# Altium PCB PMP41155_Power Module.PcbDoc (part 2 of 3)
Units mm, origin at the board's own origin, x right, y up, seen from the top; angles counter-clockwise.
Board outline 40.5 x 74.05 mm, 8 copper layers (Top Layer, Layer 1, Layer 2, Layer 3, Layer 4, Layer 5, Layer 6, Bottom Layer), stack 1.58 mm thick; 130 components, 51 nets, 407 pads, 560 vias.
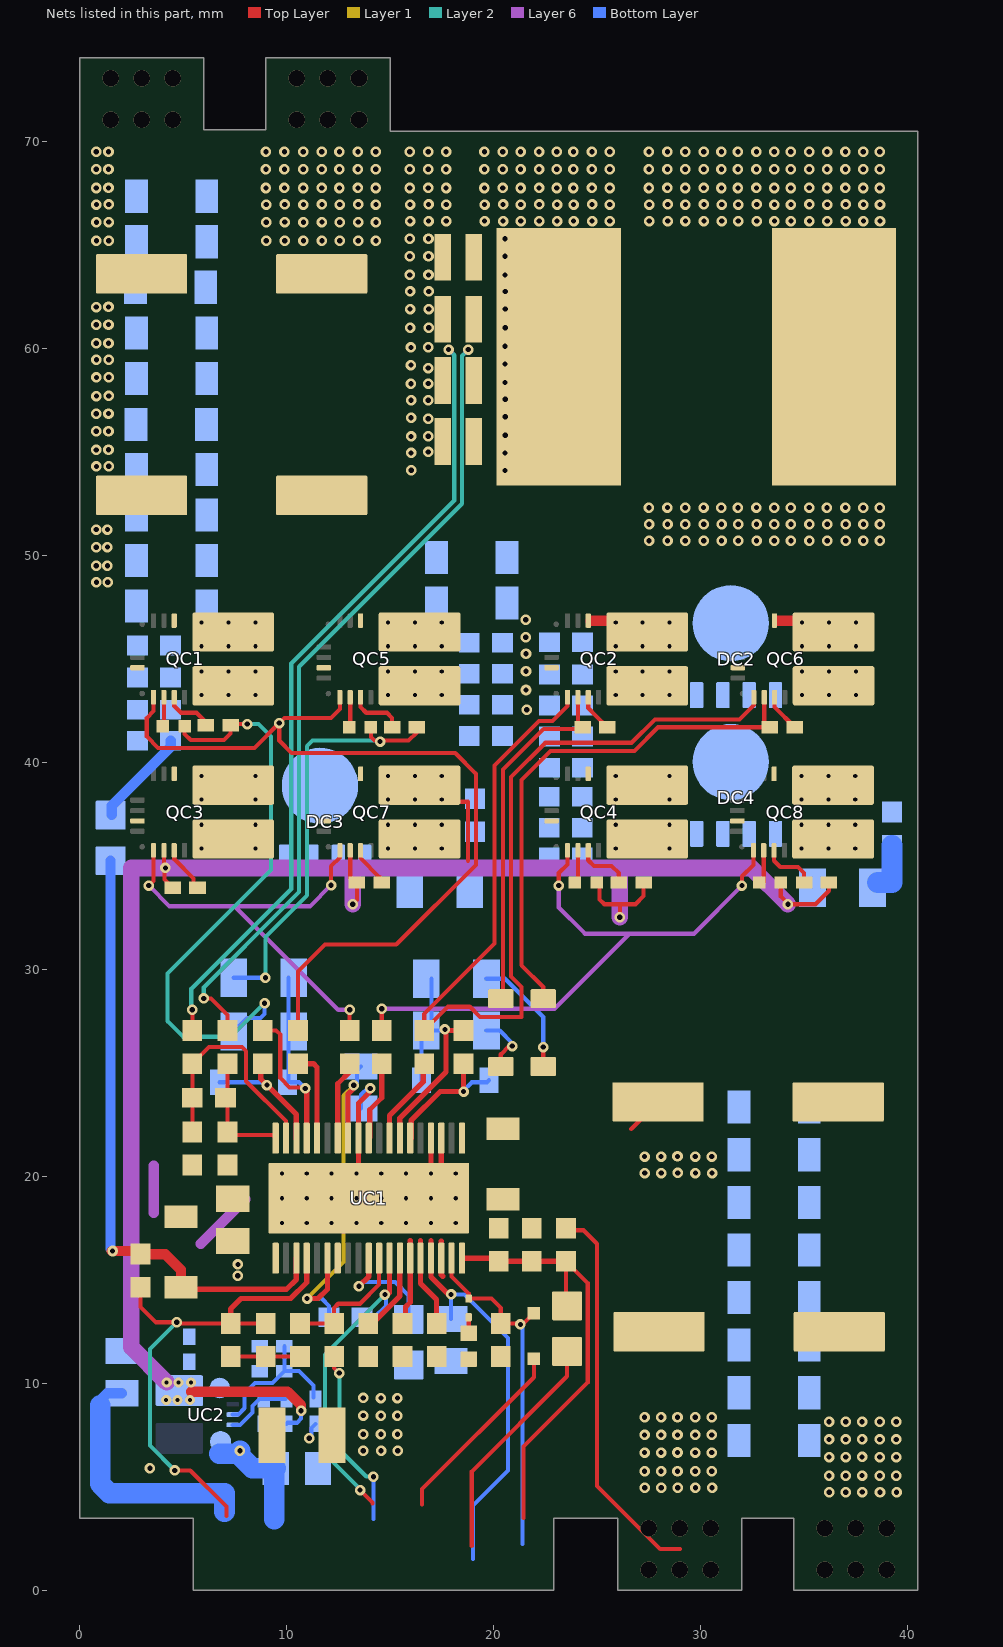
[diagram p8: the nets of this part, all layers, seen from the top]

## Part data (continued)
CC47: "CAP, CERM, 68 pF, 50 V,+/- 5%, C0G/NP0, 0603", Cap_Case=0603, Manufacturer=AVX, Supplier Part Number 1=478-1173-1-ND, TempCo=C0G/NP0, Tolerance_%=5, Value1="0.144 ohm", Value2=50V, ValueDisplayed=68pF
CC49: "CAP, CERM, 1000 pF, 50 V,+/- 5%, C0G/NP0, 0603", Cap_Case=0603, Manufacturer=MuRata, Supplier Part Number 1=490-1451-1-ND, TempCo=C0G/NP0, Tolerance_%=5, Value2=50V, ValueDisplayed=1000pF
CC50 CC51: library part CMP-0006939-4, "CAP, CERM, 47 pF, 50 V, +/- 5%, C0G/NP0, 0603", Cap_Case=0603, Manufacturer=Kemet, Supplier Part Number 1=399-1056-1-ND, TempCo=C0G/NP0, Tolerance_%=5%, Value1=Unknown, Value2=50V, ValueDisplayed=47pF
CC52: "CAP, CERM, 2200 pF, 50 V,+/- 10%, X5R, 0603", Cap_Case=0603, Manufacturer=MuRata, Supplier Part Number 1=GRM188R61H222KA01D-ND, TempCo=X5R, Tolerance_%=10, Value2=50V, ValueDisplayed=2200pF
CC53 CC54: library part CMP-0007135-4, "CAP, CERM, 0.1 uF, 16 V, +/- 10%, X7R, AEC-Q200 Grade 1, 0603", Cap_Case=0603, Manufacturer=MuRata, Supplier Part Number 1=490-8015-1-ND, TempCo=X7R, Tolerance_%=10%, Value1=Unknown, Value2=16V, ValueDisplayed=0.1uF
CC55: library part CMP-0009211-1, "CAP, CERM, 47 uF, 16 V, +/- 10%, X5R, 1210", Cap_Case=1210, Manufacturer=MuRata, Supplier Part Number 1=GRM32ER61C476KE15L-ND, TempCo=X5R, Tolerance_%=10%, Value1=Unknown, Value2=16V, ValueDisplayed=47uF
CC56: library part CMP-0007728-2, "CAP, CERM, 1 uF, 25 V, +/- 10%, X7R, 0805", Cap_Case=0805, Manufacturer=Kemet, Supplier Part Number 1=399-8004-1-ND, TempCo=X7R, Tolerance_%=10%, Value1=Unknown, Value2=25V, ValueDisplayed=1uF
CC57: library part CMP-0007989-2, "CAP, CERM, 22 uF, 6.3 V, +/- 10%, X5R, 0805", Cap_Case=0805, Manufacturer="Samsung Electro-Mechanics", TempCo=X5R, Tolerance_%=10%, Value1=Unknown, Value2=6.3V, ValueDisplayed=22uF
CC58: "CAP, CERM, 0.1uF, 6.3V, +/-10%, X7R, 0402", Cap_Case=0402, Manufacturer=MuRata, Supplier Part Number 1=GRM155R70J104KA01D-ND, TempCo=X7R, Tolerance_%=10, Value1=Unknown, Value2=6.3V, ValueDisplayed=0.1uF
CC59: library part CMP-0078218-1, "CAP, CERM, 0.01 µF, 16 V,+/- 10%, X7R, 0402", Cap_Case=0402, Manufacturer=Kemet, Supplier Part Number 1=399-1038-1-ND, TempCo=X7R, Tolerance_%=10%, Value2=16V, ValueDisplayed=0.01µF
CC60: library part CMP-0095696-1, "Cap Ceramic 22nF 50V X7R ±10% Pad SMD 0603 +125°C T/R", Manufacturer=Samsung, Operating Temperature Range="-55°C to +125°C", TempCo=0.15, Temperature Characteristic=X7R, Tolerance_%=10%, ValueDisplayed=22nF
CC61: library part CMP-0007168-4, "CAP, CERM, 820 pF, 25 V, +/- 5%, C0G/NP0, 0603", Cap_Case=0603, Manufacturer=MuRata, Supplier Part Number 1=81-GRM185C1E821JA01D, TempCo=C0G/NP0, Tolerance_%=5%, Value1=Unknown, Value2=25V, ValueDisplayed=820pF
CC62: library part CMP-0007572-2, "CAP, CERM, 0.22 uF, 25 V, +/- 20%, X7R, 0805", Cap_Case=0805, Manufacturer=AVX, Supplier Part Number 1=478-3757-1-ND, TempCo=X7R, Tolerance_%=20%, Value1="0.016 ohm", Value2=25V, ValueDisplayed=0.22uF
D1: library part CMP-0029006-2, "Diode, Ultrafast, 100 V, 0.25 A, SOD-323", Manufacturer=Nexperia, Value1=0.25A, Value2=1.4V
DC1 DC7: library part CMP-0090564-1, "Diode Schottky 40V 500mA Surface Mount SOD-123", Digikey Part Number=NRVB0540T1GOSCT-ND, Forward Current=0.5A, Manufacturer="On Semiconductor", Max Surge Forward Current=5.5A, Mouser Part Number=863-NRVB0540T1G, Operating Temperature Range="-55°C to +150°C", Peak Reverse Current=20uA
DC2 DC3 DC4: library part CMP-0032275-1, "Diode 100 V 30A Surface Mount PowerFlat™ (5x6)", Digikey Part Number=497-10342-1-ND, Forward Current=30A, Manufacturer=STMicroelectronics, Max Surge Forward Current=200A, Mouser Part Number=511-STPS30M100DJF-TR, Operating Temperature Range="to +150°C", Peak Reverse Current=100uA
DC5 DC6: library part CMP-0077600-3, "Diode, Zener, 5.6 V, 500 mW, SOD-123", Manufacturer=Vishay-Semiconductor, Power_W=500mW, Value1=0.5W
LC1: library part CMP-0064042-1, ValueDisplayed=2.2uH
LOGO1: library part CMP-0074837-1, "IEC 61010-1 Hot Surface Warning"
Logo2: library part Pb-Free
Logo3: library part CMP-0074769-1
Logo4: library part CMP-0074847-1, "FCC_disclaimer"
QC1 QC2 QC3 QC4 QC5 QC6 QC7 QC8: library part CMP-0037654-1, "100-V, 64-A GaN with Integrated Driver", Manufacturer="Texas Instruments", Max Supply Voltage=5.25V, Min Supply Voltage=4.75V, Nominal Supply Current=3mA, Operating Temperature Range="-40°C to +125°C"
R1 R2 R7 R8: library part CMP-02407-004899-1, "RES Thick Film, 3.01Ω, 1%, 0.063W, 200ppm/°C, 0402", Case Code (Imperial)=0402, Case Code (Metric)=1005, Max Operating Temperature=155°C, Max Power Dissipation=63mW, Min Operating Temperature=-55°C, Package Quantity=10000, Resistance=3.01R, Temperature Coefficient=200ppm/°C, Tolerance=1%, Voltage Rating=50V
R3 R4: library part CMP-0016888-3, "RES, 2.55, 1%, 0.25 W, AEC-Q200 Grade 0, 1206", Manufacturer=Vishay-Dale, Power_W=250mW, Supplier Part Number 1=541-2.55FFCT-ND, TempCo="100 ppm/C", Tolerance_%=1%, Value2=0.25W, Value_Code=2R55, ValueDisplayed=2.55
R5: library part CMP-0022550-4, "RES, 681 k, 1%, 0.1 W, AEC-Q200 Grade 0, 0603", Manufacturer=Vishay-Dale, Power_W=100mW, Supplier Part Number 1=541-681KHCT-ND, TempCo="100 ppm/C", Tolerance_%=1%, Value2=0.1W, Value_Code=681k
R6: library part CMP-0022042-4, "RES, 13.0 k, 1%, 0.1 W, AEC-Q200 Grade 0, 0603", Manufacturer=Vishay-Dale, Power_W=100mW, Supplier Part Number 1=541-13.0KHCT-ND, TempCo="100 ppm/C", Tolerance_%=1%, Value2=0.1W, Value_Code=13k0, ValueDisplayed=13.0k
RC1 RC2 RC26 RC27: library part CMP-0018270-2, "RES, 3.30, 1%, 0.25 W, 1206", Manufacturer="Yageo America", Power_W=250mW, Supplier Part Number 1=311-3.30FRCT-ND, TempCo="200 ppm/C", Tolerance_%=1%, Value2=0.25W, Value_Code=3R30, ValueDisplayed=3.30
RC3 RC4 RC28 RC29: library part CMP-0015357-3, "RES, 0.002, 2%, 1 W, 0508", Manufacturer="Susumu Co Ltd", Power_W=1W, Supplier Part Number 1=408-1592-1-ND, TempCo="100 ppm/C", Tolerance_%=2%, Value_Code=2L000, ValueDisplayed=0.002
RC5 RC6 RC18: library part CMP-0096818-1, "0 Ohms Jumper 0.245W Chip Resistor 0805 (2012 Metric) - Metal Element", Digikey Part Number=JR0805X35ECT-ND, Manufacturer=Ohmite, Mouser Part Number=588-JR0805X35E, Operating Temperature Range="-55°C to +150°C", Power_W=245mW
RC7: "RES, 270 k, 5%, 0.1 W, 0603", Manufacturer=Vishay-Dale, Power_W=0.1, Supplier Part Number 1=541-270KGCT-ND, TempCo="200 ppm/C", Tolerance_%=5, Value1=5%, Value2=0.1W, Value_Code=270k
RC8 RC10: "RES, 100, 1%, 0.1 W, 0603", Manufacturer="Yageo America", Power_W=0.1, Supplier Part Number 1=311-100HRCT-ND, TempCo="200 ppm/C", Tolerance_%=1, Value1=1%, Value2=0.1W, Value_Code=100R, ValueDisplayed=100
RC9: "RES, 10.0 k, 1%, 0.1 W, 0603", Manufacturer=Vishay-Dale, Power_W=0.1, Supplier Part Number 1=541-10.0KHCT-ND, TempCo="100 ppm/C", Tolerance_%=1, Value1=1%, Value2=0.1W, Value_Code=10k0, ValueDisplayed=10.0k
RC11: "RES, 100, 1%, 0.1 W, 0603", Manufacturer=Vishay-Dale, Power_W=0.1, Supplier Part Number 1=541-100HCT-ND, TempCo="100 ppm/C", Tolerance_%=1, Value1=1%, Value2=0.1W, Value_Code=100R, ValueDisplayed=100
RC12: "RES, 10.7 k, 1%, 0.1 W, 0603", Manufacturer=Vishay-Dale, Power_W=0.1, Supplier Part Number 1=541-10.7KHCT-ND, TempCo="100 ppm/C", Tolerance_%=1, Value1=1%, Value2=0.1W, Value_Code=10k7, ValueDisplayed=10.7k
RC13 RC14 RC16 RC19: library part CMP-0025697-4, "RES, 0, 5%, 0.1 W, AEC-Q200 Grade 0, 0603", Manufacturer=Vishay-Dale, Power_W=100mW, Supplier Part Number 1=541-0.0GCT-ND, TempCo="200 ppm/C", Tolerance_%=5%, Value2=0.1W, Value_Code=0000, ValueDisplayed=0
RC15: library part CMP-0026403-2, "RES, 49.9 k, 1%, 0.063 W, AEC-Q200 Grade 0, 0402", Manufacturer=Vishay-Dale, Power_W=63mW, Supplier Part Number 1=541-49.9KLCT-ND, TempCo="100 ppm/C", Tolerance_%=1%, Value2=0.063W, Value_Code=49k9, ValueDisplayed=49.9k
RC17: library part CMP-0026728-1, "RES, 220 k, 1%, 0.0625 W, 0402", Manufacturer="Yageo America", Power_W=62.5mW, Supplier Part Number 1=311-220KLRCT-ND, TempCo="100 ppm/C", Tolerance_%=1%, Value2=0.0625W, Value_Code=220k
RC20 RC21: library part CMP-0078244-2, "RES, 30.0 k, 1%, 0.063 W, AEC-Q200 Grade 0, 0402", Manufacturer=Vishay-Dale, Power_W=63mW, Supplier Part Number 1=541-30.0KLCT-ND, TempCo="100 ppm/C", Tolerance_%=1%, Value2=0.063W, Value_Code=30k0, ValueDisplayed=30.0k
RC22: library part CMP-0089989-1, "2.87 kOhms ±1% 0.1W, 1/10W Chip Resistor 0402 (1005 Metric) Automotive AEC-Q200, Moisture Resistant Thick Film", Digikey Part Number=2019-RK73H1ETTP2871FCT-ND, Manufacturer="KOA Speer", Mouser Part Number=660-RK73H1ETTP2871F, Operating Temperature Range="-55°C to +155°C", Power_W=100mW, TempCo=100ppm/°C, Tolerance_%=1%
RC23: "RES, 8.25 k, 1%, 0.1 W, 0603", Manufacturer=Vishay-Dale, Power_W=0.1, Supplier Part Number 1=541-8.25KHCT-ND, TempCo="100 ppm/C", Tolerance_%=1, Value1=1%, Value2=0.1W, Value_Code=8k25, ValueDisplayed=8.25k
RC24: "RES, 100 k, 1%, 0.1 W, 0603", Manufacturer=Vishay-Dale, Power_W=0.1, Supplier Part Number 1=541-100KHCT-ND, TempCo="100 ppm/C", Tolerance_%=1, Value1=1%, Value2=0.1W, Value_Code=100k
RC25: library part CMP-0022064-4, "RES, 158 k, 1%, 0.1 W, AEC-Q200 Grade 0, 0603", Manufacturer=Vishay-Dale, Power_W=100mW, Supplier Part Number 1=541-158KHCT-ND, TempCo="100 ppm/C", Tolerance_%=1%, Value2=0.1W, Value_Code=158k
UC1: library part CMP-0094661-2, "Wide VIN Bidirectional 4 Switch Buck-Boost Controller", Manufacturer="Texas Instruments", Max Supply Voltage=78V, Min Supply Voltage=2.8V, Nominal Supply Current=25uA, Operating Temperature Range="-40°C to +125°C", Output Voltage=3.3-78V, Switching Frequency=100-2000kHz
UC2: library part CMP-0097277-1, "3V to 16 V Input, 3-A Synchronous Step-Down Voltage Regulator Module, QFN-FCMOD7", Manufacturer="Texas Instruments", Max Supply Voltage=16V, Min Supply Voltage=3V, Nominal Supply Current=120-400uA, Operating Temperature Range="-40°C to +125°C", Output Voltage=0.6-7V, Switching Frequency=1400/2000kHz

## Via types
v1: diameter 0.508, hole 0.254, Top Layer to Bottom Layer, 408 vias
v2: diameter 0.5, hole 0.2, Top Layer to Bottom Layer, tented both sides, 88 vias
v3: diameter 0.5, hole 0.2, Top Layer to Bottom Layer, 36 vias
v4: diameter 0.8, hole 0.8, Top Layer to Bottom Layer, 24 vias
v5: diameter 0.508/0.508/0.508/0.508/0.508/0.508/0.508/0.508 (per signal layer), hole 0.254, Top Layer to Bottom Layer, 4 vias

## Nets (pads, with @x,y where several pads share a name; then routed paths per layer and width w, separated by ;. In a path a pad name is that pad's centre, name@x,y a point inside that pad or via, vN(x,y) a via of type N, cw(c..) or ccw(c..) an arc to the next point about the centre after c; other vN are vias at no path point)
5V: CC41.1 CC42.1 CC57.1 CC58.1 CC65.1 CC66.1 QC3.3 QC7.3 R2.2 R8.2 RC17.2 UC2.3 | length 95.1
  Top Layer w0.2: QC3.3@4.075,35.75 4.075,34.975 v1(4.15,34.9) 4.1,34.85 4.1,34.35 CC41.1@4.3,34.15 ; 5.385,9.6 v3(5.385,10.05) ; QC7.3@13.075,35.75 13.075,34.425 CC65.1@13.3,34.2 ; v1(13.2,33.15) 13.4,33.35 13.4,34 13.3,34.1 CC65.1@13.4,34.2 ; R2.2@25.125,34.2 25.125,33.375 25.35,33.15 26.1,33.15 ; v1(26.1,32.518) 26.1,33.15 ; CC42.1@27.25,34.2 27.25,33.55 26.85,33.15 26.1,33.15 ; R8.2@33.875,34.2 33.875,33.525 v1@34.25,33.15 ; v1(34.218,33.15) v1@34.234,33.166 ; v1@34.35,33.15 35.55,33.15 36.2,33.8 CC66.1@36.2,34.2
  Top Layer w0.5: 5.385,9.6 10.05,9.6 10.7,8.95 v1(10.7,8.687)
  Layer 6 w0.5: 22.25,34.75 22.4,34.9 ; v1@26.096,32.522 v1(26.1,32.518)
  Layer 6 w0.8: v3(4.21,10.05) 2.5,11.76 2.5,34.9 v1(4.15,34.9) 13.2,34.9 ; v1(13.2,33.15) 13.2,34.9 ; v1(26.1,32.518) 26.1,34.9 ; v1(34.218,33.15) 32.468,34.9 26.1,34.9 ; 13.2,34.9 22.4,34.9 26.1,34.9
  Bottom Layer w0.2: RC17.2@10,8.05 10.05,8.1 10.5,8.1 10.7,8.3 v1(10.7,8.687)
  Bottom Layer w0.5: 0.75,8.95 1.334,9.534 CC57.1@2.05,9.534
  Bottom Layer w1: 1,8.95 1,5.15 1.45,4.7 7,4.7 7,3.8
  other v3: 4.185,9.2 4.735,9.2 5.335,9.2 4.785,10.05
12V: CC45.2 CC55.1 CC56.1 RC15.2 UC1.1 UC2.1 | length 6.8
  Top Layer w0.2: v1@11,7.4 v1@11.05,7.35
  Bottom Layer w0.2: CC56.1@9.484,5.9 CC56.1@9.8,5.584 ; v1(11.1,7.35) 11.2,7.45 11.2,7.85 RC15.2@11.4,8.05
  Bottom Layer w1: 6.75,6.6 7.6,6.6 v1(7.75,6.75) 7.65,6.65 7.65,6.6 8.35,5.9 CC56.1@9.484,5.9 ; 9.4,3.45 CC56.1@9.4,5.484
  other v1: 7.649,15.199 7.65,15.75
COMP: CC61.1 D1.2 RC22.2 UC1.18 | length 17.3
  Top Layer w0.2: UC1.18@17.975,16.05 17.975,15.175 18.8,14.35 RC22.2@18.8,14.1 19.9,14.1 20.35,13.65 CC61.1@20.35,12.9 21.25,12.9 v1(21.3,12.85) 21.4,12.85 D1.2@21.95,13.4
  Bottom Layer w0.2: v1(21.3,12.85) 21.4,12.75 21.4,2.25
COMP_DIR: D1.1 | length 9.3
  Top Layer w0.2: 16.55,4.15 16.55,4.9 21.95,10.3 D1.1@21.95,11.2
CSA_DISCH: C2.1 CC28.2 CC53.1 CC63.2 DC3.5 DC5.2 QC1.4 QC1.6 QC1.14 QC3.7 QC3.8 QC5.4 QC5.6 QC5.14 QC7.7 QC7.8 RC3.1 RC4.1 RC8.2 RC28.1 RC29.1 UC1.36 | length 55.6
  Top Layer w0.2: QC1.4@4.575,43.15 4.575,42.725 4.9,42.4 5.65,42.4 6.1,41.95 CC28.2@6.1,41.8 ; RC8.2@5.45,27.05 v1(5.45,28.05) ; QC5.4@13.575,43.15 13.575,42.675 13.85,42.4 14.85,42.4 15.1,42.15 CC63.2@15.1,41.7 ; QC7.7@16.425,38.9 17.225,38.1 18.772,38.1 18.772,35.25
  Top Layer w0.254: CC53.1@8.75,25.45 8.75,24.721 v1(9.055,24.416) 10.475,22.996 UC1.36@10.475,21.85
  Layer 2 w0.2: v1(5.45,28.05) 5.4,28.1 5.4,29.066 10.228,33.894 10.228,42.074 10.228,44.778 18.1,52.65 18.1,59.67 v1(17.828,59.942)
  Bottom Layer w0.2: DC5.2@6.763,24.55 8.921,24.55 v1(9.055,24.416)
  other v1: 16.028,54.118 16.018,54.948 16.85,55 16.018,55.748 16.85,55.75 16.85,56.6 16.018,56.648 16.018,57.498 16.85,57.5 16.008,58.296 16.85,58.3 16.85,59.05 16.008,59.196 16.008,60.046 16.85,60.05 15.968,60.998 16.868,60.998 15.968,61.898 16.868,61.898 15.968,62.748 16.868,62.748 15.958,63.546 16.858,63.546 15.958,64.446 16.858,64.446 15.958,65.296 16.858,65.296 15.968,66.148 16.86,66.152 17.718,66.148 15.968,66.948 16.86,66.952 17.718,66.948 15.958,67.746 16.85,67.75 17.708,67.746 15.958,68.646 16.85,68.65 17.708,68.646 15.958,69.496 16.85,69.5 17.708,69.496
  other v2: 5.9,38.21 8.5,38.21 14.9,38.21 16.2,38.21 17.5,38.21 5.9,39.35 8.5,39.35 14.9,39.35 16.2,39.35 17.5,39.35 5.9,43.25 7.2,43.25 8.5,43.25 14.9,43.25 16.2,43.25 17.5,43.25 5.9,44.39 7.2,44.39 8.5,44.39 14.9,44.39 16.2,44.39 17.5,44.39
CSB_DISCH: LC1.1 RC3.2 RC4.2 RC10.2 RC28.2 RC29.2 | length 38.9
  Top Layer w0.2: v5(6,28.6) 6.35,28.6 7.15,27.8 RC10.2@7.15,27.05
  Layer 2 w0.2: v5(6,28.6) 6,29.131 10.05,33.181 10.606,33.737 10.606,40.94 10.606,44.621 18.478,52.494 18.478,52.678 18.478,59.641 v1(18.778,59.942)
  other v1: 20.55,54.1 20.55,54.95 20.568,55.798 20.568,56.698 20.568,57.548 20.558,58.346 20.558,59.246 20.558,60.096 20.568,60.998 20.568,61.898 20.568,62.748 20.558,63.546 20.558,64.446 20.558,65.296 19.568,66.148 20.46,66.152 21.318,66.148 22.21,66.152 23.068,66.148 23.868,66.148 24.76,66.152 25.618,66.148 19.568,66.948 20.46,66.952 21.318,66.948 22.21,66.952 23.068,66.948 23.868,66.948 24.76,66.952 25.618,66.948 19.558,67.746 20.45,67.75 21.308,67.746 22.2,67.75 23.058,67.746 23.858,67.746 24.75,67.75 25.608,67.746 19.558,68.646 20.45,68.65 21.308,68.646 22.2,68.65 23.058,68.646 23.858,68.646 24.75,68.65 25.608,68.646 19.558,69.496 20.45,69.5 21.308,69.496 22.2,69.5 23.058,69.496 23.858,69.496 24.75,69.5 25.608,69.496
DISCH_SS: CC62.1 UC1.16 | length 19.4
  Top Layer w0.254: 16.975,16.9 UC1.16@16.975,16.05 16.975,15.143 17.868,14.25 v1@18.05,14.25
  Bottom Layer w0.2: v1(17.949,14.299) 18.601,14.299 20.7,12.2 20.7,5.8 19,4.1 19,2.25 19,1.527 ; CC62.1@17.95,13.116 v1@17.95,14.298
DTRK_DISCH: RC18.2 UC1.10 | length 5.4
  Top Layer w0.254: v1(13.5,14.7) 13.975,15.175 UC1.10@13.975,16.05
  Bottom Layer w0.2: v1(13.5,14.7) 13.7,14.9 15.25,14.9 15.9,14.25 RC18.2@15.9,13.1
FB_DIR: RC6.2 | length 11.3
  Top Layer w0.2: 18.95,2.15 18.95,5.75 23.55,10.35 RC6.2@23.55,11.55
GHA: QC1.2 QC5.2 RC13.2 | length 41.9
  Top Layer w0.2: QC1.2@3.575,43.15 3.575,42.475 3.25,42.15 3.25,41.25 3.8,40.7 8.45,40.7 v1(9.65,41.9) ; RC13.2@10.55,27.05 10.55,28.9 10.55,29.9 11.85,31.2 15.3,31.2 19.15,35.05 19.15,39.45 18.15,40.45 16.4,40.45 10.25,40.45 9.65,41.05 v1(9.65,41.9) ; QC5.2@12.575,43.15 12.575,42.575 12.15,42.15 9.9,42.15 v1(9.65,41.9)
GHB: QC2.2 QC6.2 RC16.2 | length 50.1
  Top Layer w0.2: QC2.2@23.575,43.15 23.575,42.725 22.85,42 22.2,42 20.05,39.85 20.05,31.25 16.65,27.85 RC16.2@16.65,27.05 17.8,28.2 18.85,28.2 19.35,27.7 21.35,27.7 21.35,29.15 20.85,29.65 20.85,39.3 22.5,40.95 26.666,40.95 27.794,42.078 27.978,42.078 28.228,42.078 31.878,42.078 32.575,42.775 QC6.2@32.575,43.15
GLA: QC3.2 QC7.2 RC14.2 | length 21.9
  Top Layer w0.2: v1(3.35,34.05) 3.575,34.275 QC3.2@3.575,35.75 ; v1(12.15,34.068) 12.15,34.1 12.15,34.986 12.575,35.411 QC7.2@12.575,35.75 ; RC14.2@13.05,27.05 v1(13.05,28.05)
  Layer 6 w0.2: v1(3.35,34.05) 4.35,33.05 7.5,33.05 ; v1(12.15,34.068) 11.132,33.05 7.5,33.05 ; v1(13.05,28.05) 12.5,28.05 7.5,33.05
GLB: QC4.2 QC8.2 RC19.2 | length 29.8
  Top Layer w0.2: RC19.2@14.6,27.05 v1(14.6,28.1) ; v1(23.15,34.05) 23.15,34.65 23.575,35.075 QC4.2@23.575,35.75 ; v1(32,34.05) 32,34.5 32.55,35.05 QC8.2@32.55,35.75
  Top Layer w0.254: RC19.2@14.54,26.9 RC19.2@14.6,26.9
  Layer 6 w0.2: v1(14.6,28.1) 22.95,28.1 26.575,31.725 ; v1(23.15,34.05) 23.15,33 24.3,31.85 24.425,31.725 26.575,31.725 ; v1(32,34.05) 29.675,31.725 26.575,31.725
HB1: CC53.2 DC5.1 RC1.1 RC26.1 UC1.35 | length 13
  Top Layer w0.2: CC53.2@8.75,27.05 9.5,27.05 9.7,26.85 9.7,24.75 10.15,24.3 10.85,24.3 v1(10.9,24.25)
  Top Layer w0.254: UC1.35@10.975,21.85 v1@10.975,24.225
  Bottom Layer w0.2: RC26.1@10.1,29.6 10.1,27 10.1,24.612 DC5.1@10.038,24.55 10.6,24.55 v1(10.9,24.25)
HB2: CC54.2 DC6.1 RC2.2 RC27.2 UC1.26 | length 13
  Top Layer w0.254: UC1.26@15.475,21.85 15.475,22.825 17.7,25.05 17.7,27 v1@17.6,27.1 ; v1(17.65,27.1) 17.7,27.05 CC54.2@18.55,27.05
  Bottom Layer w0.2: DC6.1@16.512,24.65 16.512,26.812 RC2.2@16.75,27.05 RC2.2@17,27.05 ; RC27.2@17,29.55 RC2.2@17,27.05 ; v1@17.6,27.1 17.55,27.05 RC2.2@17,27.05
MODE: RC9.2 UC1.12 | length 16.2
  Top Layer w0.2: v1(13.55,4.85) 14.15,4.25 14.15,4.2
  Top Layer w0.254: v1(14.755,14.295) 14.755,14.25 14.839,14.25 14.975,14.386 UC1.12@14.975,16.05
  Layer 2 w0.2: v1(13.55,4.85) 13.55,4.9 11.85,6.6 11.85,11.39 v1(14.755,14.295)
  Bottom Layer w0.2: RC9.2@13.65,13.2 14.25,13.2 14.8,13.75 14.8,14.25 v1(14.755,14.295)
NetC1_2: C1.2 R3.2 | length 3.2
  Bottom Layer w0.2: R3.2@38.3,33.95 R3.2@38.55,34.2 ; C1.2@39.25,36 C1.2@39.5,35.75
  Bottom Layer w1: R3.2@38.55,34.2 39.25,34.2 C1.2@39.25,36
NetC2_2: C2.2 R4.2
NetCC28_1: CC28.1 R1.1 RC1.2 | length 29.3
  Top Layer w0.2: R1.1@5.075,41.75 5.075,41.375 5.372,41.078 6.978,41.078 7.3,41.4 CC28.1@7.3,41.8 7.35,41.85 v5(8.1,41.85)
  Layer 2 w0.2: v5(8.1,41.85) 8.651,41.849 9.25,41.25 9.25,34.8 4.25,29.8 4.25,27.5 5,26.75 7.318,26.75 v5(8.94,28.372)
  Bottom Layer w0.2: RC1.2@7.45,27 8.1,27.65 8.75,27.65 8.94,27.84 v5(8.94,28.372)
NetCC29_1: CC29.1 DC1.1 QC2.3 | length 17.3
  Top Layer w0.2: DC1.1@20.35,28.588 20.45,28.688 20.45,39.65 22.422,41.622 23.006,41.622 24.222,41.622 CC29.1@24.3,41.7 24.075,41.925 QC2.3@24.075,43.15
NetCC47_1: CC47.1 CC50.1 RC8.1 UC1.37 | length 11.3
  Top Layer w0.2: CC50.1@5.45,22.15 CC47.1@5.45,23.8 RC8.1@5.45,25.45 6.25,26.25 7.85,26.25 8.05,26.05 8.05,24.6 9.975,22.675 UC1.37@9.975,21.85
NetCC47_2: CC47.2 CC51.1 RC10.1 UC1.38 | length 6
  Top Layer w0.2: RC10.1@7.05,25.35 RC10.1@7.15,25.45 7.15,23.9 CC47.2@7.05,23.8 7.15,23.7 CC51.1@7.15,22.15 7.3,22 9.325,22 UC1.38@9.475,21.85
NetCC48_1: CC48.1 RC5.2 RC7.2 UC1.3 | length 30.3
  Top Layer w0.2: RC7.2@2.8,16.4 RC7.2@2.95,16.25
  Top Layer w0.254: CC48.1@4.9,14.65 5,14.55 10,14.55 10.475,15.025 UC1.3@10.475,16.05
  Top Layer w0.5: v1@1.55,16.4 RC7.2@2.8,16.4 ; RC7.2@2.95,16.25 3.2,16.25 4.15,16.25 4.9,15.5 CC48.1@4.9,14.65
  Bottom Layer w0.2: v1@1.5,16.498 v1(1.599,16.399)
  Bottom Layer w0.5: v1@1.5,16.498 RC5.2@1.5,35.25
NetCC52_2: CC52.2 RC11.2 UC1.11 | length 6.3
  Top Layer w0.2: CC52.2@10.65,12.9 RC11.2@12.3,12.9 12.3,13.65 12.5,13.85 13.55,13.85 14.475,14.775 UC1.11@14.475,16.05
NetCC59_1: CC59.1 RC15.1 RC21.2 UC2.6 | length 7.3
  Bottom Layer w0.2: UC2.6@7.4,8.5 7.674,8.5 7.978,8.804 7.978,9.528 8.472,10.022 9.322,10.022 CC59.1@9.9,10.6 ; RC21.2@9.9,11.8 CC59.1@9.9,10.6 ; RC15.1@11.3,9.322 11.3,9.9 10.6,10.6 CC59.1@9.9,10.6
NetCC60_2: CC60.2 RC22.1 | length 0.8
  Top Layer w0.2: CC60.2@18.8,12.427 RC22.1@18.8,13.2
NetCC63_1: CC63.1 R7.1 RC26.2 | length 20.6
  Top Layer w0.2: R7.1@14.075,41.7 14.075,41.225 14.25,41.05 v1@14.519,41.05 ; v1(14.519,41.008) v1@14.519,41.05 ; CC63.1@16.3,41.7 16.3,41.45 15.9,41.05 v1@14.519,41.05
  Layer 2 w0.2: v5(8.979,29.6) 8.979,31.576 10.983,33.581 10.983,40.783 11.25,41.05 13.95,41.05 14.477,41.05 v1(14.519,41.008)
  Bottom Layer w0.2: RC26.2@7.45,29.6 v5@9.1,29.6
NetCC64_1: CC64.1 DC7.1 QC6.3 | length 25.6
  Top Layer w0.2: DC7.1@22.4,28.588 22.4,29.15 21.35,30.2 21.35,39.15 22.75,40.55 24.824,40.55 26.8,40.55 27.95,41.7 CC64.1@33.35,41.7 33.075,41.975 QC6.3@33.075,43.15
NetDC1_2: DC1.2 RC2.1 | length 3
  Top Layer w0.2: DC1.2@20.35,25.312 20.35,25.9 20.75,26.3 v1(20.9,26.3)
  Bottom Layer w0.2: RC2.1@19.65,27.05 20.3,27.05 20.9,26.45 v1(20.9,26.3)
NetDC7_2: DC7.2 RC27.1 | length 5.9
  Top Layer w0.2: DC7.2@22.4,25.312 v1(22.4,26.25)
  Bottom Layer w0.2: RC27.1@19.65,29.55 20.55,29.55 22.4,27.7 v1(22.4,26.25)
NetQC1_3: QC1.3 R1.2 | length 1.4
  Top Layer w0.2: R1.2@4.025,41.75 4.075,41.8 QC1.3@4.075,43.15
NetQC4_3: QC4.3 R2.1 | length 1.6
  Top Layer w0.2: R2.1@24.075,34.2 QC4.3@24.075,35.75
NetQC5_3: QC5.3 R7.2 | length 1.5
  Top Layer w0.2: R7.2@13.025,41.7 13.075,41.75 QC5.3@13.075,43.15
NetQC8_3: QC8.3 R8.1 | length 1.6
  Top Layer w0.2: R8.1@33.025,34.2 33.05,34.225 QC8.3@33.05,35.75
NetRC13_1: RC13.1 UC1.34 | length 4.4
  Top Layer w0.254: RC13.1@10.55,25.45 11.3,25.45 11.475,25.275 UC1.34@11.475,21.85
NetRC14_1: RC14.1 UC1.32 | length 3.8
  Top Layer w0.254: UC1.32@12.481,21.85 UC1.32@12.475,21.85 12.475,24.183 12.475,24.475 13.05,25.05 RC14.1@13.05,25.45
NetRC16_1: RC16.1 UC1.27 | length 4.3
  Top Layer w0.254: UC1.27@14.975,21.85 14.975,22.936 16.6,24.561 RC16.1@16.6,25.45
NetRC17_1: RC17.1 RC20.2 UC2.7 | length 3.2
  Bottom Layer w0.2: UC2.7@7.4,8 7.757,8 8.356,8.598 8.356,8.906 8.7,9.25 RC20.2@8.9,9.25 RC17.1@9.95,9.25
NetRC19_1: RC19.1 UC1.29 | length 3.9
  Top Layer w0.254: UC1.29@13.975,21.85 14.02,21.895 14.02,23.22 14.6,23.8 RC19.1@14.6,25.45
NetRC23_2: RC23.2 UC1.13 | length 3.9
  Top Layer w0.254: RC23.2@13.95,12.9 14.15,12.9 15.475,14.225 UC1.13@15.475,16.05
NetRC24_2: RC24.2 UC1.14 | length 4.2
  Top Layer w0.254: RC24.2@15.5,12.9 15.75,13.15 15.75,13.7 15.975,13.925 UC1.14@15.975,16.05 15.975,16.9
NetRC25_2: RC25.2 UC1.15 | length 4.2
  Top Layer w0.254: 16.475,16.9 UC1.15@16.475,16.05 16.475,14.825 17.25,14.05 RC25.2@17.25,13
nFLT_DISCH: UC1.7
PWMH_SYNC: RC11.1 | length 8.9
  Top Layer w0.2: RC11.1@12.3,11.3 12.3,10.75 v1(12.55,10.5)
  Top Layer w0.254: RC11.1@12.3,11.3 RC11.1@12.4,11.3
  Layer 2 w0.2: v1(12.55,10.5) 12.55,6.8 13.85,5.5 v1(14.2,5.5)
  Bottom Layer w0.2: 14.2,3.45 v1(14.2,5.5)
SGND: CC1.2 CC2.2 CC3.2 CC4.2 CC5.2 CC6.2 CC7.2 CC8.2 CC9.2 CC10.2 CC11.2 CC12.2 CC13.2 CC14.2 CC15.2 CC16.2 CC17.2 CC18.2 CC19.2 CC20.2 CC21.2 CC22.2 CC23.2 CC24.2 CC25.2 CC26.2 CC27.2 CC30.1 CC31.1 CC32.2 CC33.2 CC34.2 CC35.2 CC36.2 CC37.2 CC38.2 CC39.2 CC40.2 CC41.2 CC42.2 CC43.2 CC44.2 CC45.1 CC46.2 CC48.2 CC49.2 CC50.2 CC51.2 CC52.1 CC55.2 CC56.2 CC57.2 CC58.2 CC59.2 CC60.1 CC61.2 CC62.2 CC65.2 CC66.2 CC67.1 CC68.1 DC3.1 DC3.2 DC3.3 DC3.4 DC4.1 DC4.2 DC4.3 DC4.4 QC3.4 QC3.6 QC3.14 QC4.4 QC4.6 QC4.14 QC7.4 QC7.6 QC7.14 QC8.4 QC8.6 QC8.14 R3.1 R4.1 R6.1 RC12.1 RC18.1 RC20.1 RC21.1 RC23.1 RC24.1 RC25.1 UC1.17 UC1.22 UC1.23 UC1.30 UC1.39 UC2.4 | length 27.9
  Top Layer w0.2: QC3.4@4.575,35.75 4.575,35.325 5.5,34.4 CC41.2@5.5,34.15 ; CC49.2@7.3,11.3 RC12.1@9,11.3 CC52.1@10.65,11.3 ; QC7.4@13.575,35.75 13.575,35.375 14.5,34.45 CC65.2@14.5,34.2 ; RC23.1@14,11.275 RC23.1@14.025,11.3 ; QC4.4@24.575,35.75 24.575,35.275 24.85,35 25.7,35 26.05,34.65 CC42.2@26.05,34.2 ; QC8.4@33.55,35.75 33.55,35.25 33.85,34.95 34.7,34.95 35,34.65 CC66.2@35,34.2
  Top Layer w0.254: UC1.39@13.475,20.15 UC1.30@13.475,21.85 13.475,23.533 v1@14.041,24.099 ; RC23.1@14,11.275 RC23.1@14.05,11.275 ; UC1.39@16.975,20.589 UC1.23@16.975,21.85 ; 17.475,16.885 UC1.17@17.475,16.05 17.475,15.254 17.543,15.185 ; UC1.22@17.475,21.85 UC1.39@17.478,20.369
  Layer 6 w0.508: 3.575,18.25 3.575,20.524 ; 5.849,16.751 8,18.901
  Bottom Layer w0.2: CC44.2@13.6,23.284 13.6,23.95 13.95,24.3 14.041,24.3 v1(14.041,24.249)
  other v1: 36.218,4.748 37.018,4.748 37.81,4.752 38.668,4.748 39.468,4.748 36.208,5.546 37.008,5.546 38.658,5.546 39.458,5.546 37.8,5.55 3.399,5.899 36.208,6.446 37.008,6.446 37.8,6.45 38.658,6.446 39.458,6.446 13.71,6.752 14.568,6.748 15.368,6.748 36.208,7.296 37.008,7.296 37.8,7.3 38.658,7.296 39.458,7.296 13.7,7.55 14.558,7.546 15.358,7.546 36.208,8.146 37.008,8.146 37.8,8.15 38.658,8.146 39.458,8.146 13.7,8.45 14.558,8.446 15.358,8.446 13.7,9.3 14.558,9.296 15.358,9.296 21.608,42.546 21.568,43.498 21.568,44.398 21.568,45.248 21.558,46.046 21.558,46.896 0.818,48.698 1.36,48.702 0.808,49.496 1.35,49.5 0.808,50.396 1.35,50.4 0.808,51.246 1.35,51.25 0.818,54.298 1.41,54.302 0.808,55.096 1.4,55.1 0.808,55.996 1.4,56 0.808,56.846 1.4,56.85 0.818,57.698 1.41,57.702 0.818,58.598 1.41,58.602 0.818,59.448 1.41,59.452 0.808,60.246 1.4,60.25 0.808,61.146 1.4,61.15 0.808,61.996 1.4,62 0.818,65.198 1.41,65.202 0.818,66.098 1.41,66.102 0.818,66.948 1.41,66.952 0.808,67.746 1.4,67.75 0.808,68.646 1.4,68.65 0.808,69.496 1.4,69.5
  other v2: 5.9,35.85 8.5,35.85 14.9,35.85 16.2,35.85 17.5,35.85 25.9,35.85 28.5,35.85 34.875,35.85 36.175,35.85 37.475,35.85 5.9,36.99 8.5,36.99 14.9,36.99 16.2,36.99 17.5,36.99 25.9,36.99 28.5,36.99 34.875,36.99 36.175,36.99 37.475,36.99
  other v3: 9.775,17.75 10.975,17.75 12.175,17.75 13.375,17.75 14.575,17.75 15.775,17.75 16.975,17.75 18.175,17.75 9.775,18.95 10.975,18.95 12.175,18.95 13.375,18.95 14.575,18.95 15.775,18.95 16.975,18.95 18.175,18.95 9.775,20.15 10.975,20.15 12.175,20.15 13.375,20.15 14.575,20.15 15.775,20.15 16.975,20.15 18.175,20.15
  other v4: 36,1 37.5,1 39,1 36,3 37.5,3 39,3 1.5,71.05 3,71.05 4.5,71.05 1.5,73.05 3,73.05 4.5,73.05
SW2: C1.1 CC29.2 CC54.1 CC64.2 DC2.1 DC2.2 DC2.3 DC2.4 DC4.5 DC6.2 LC1.2 QC2.4 QC2.6 QC2.14 QC4.7 QC4.8 QC6.4 QC6.6 QC6.14 QC8.7 QC8.8 UC1.25 | length 10.5
  Top Layer w0.2: QC2.4@24.575,43.15 24.575,42.625 24.95,42.25 CC29.2@25.5,41.7 ; QC6.4@33.575,43.15 33.575,42.675 CC64.2@34.55,41.7
  Top Layer w0.254: UC1.25@15.975,21.85 16.02,21.85 16.02,22.697 17.423,24.1 v1@18.5,24.1 ; v1(18.55,24.1) CC54.1@18.55,25.45
  Bottom Layer w0.2: v1@18.5,24.1 18.95,24.55 19.687,24.55 DC6.2@19.787,24.65
  other v1: 27.515,50.706 28.407,50.71 29.265,50.706 30.157,50.71 31.015,50.706 31.815,50.706 32.707,50.71 33.565,50.706 34.365,50.706 35.257,50.71 36.115,50.706 37.007,50.71 37.865,50.706 38.665,50.706 27.515,51.506 28.407,51.51 29.265,51.506 30.157,51.51 31.015,51.506 31.815,51.506 32.707,51.51 33.565,51.506 34.365,51.506 35.257,51.51 36.115,51.506 37.007,51.51 37.865,51.506 38.665,51.506 27.505,52.304 28.397,52.308 29.255,52.304 30.147,52.308 31.005,52.304 31.805,52.304 32.697,52.308 33.555,52.304 34.355,52.304 35.247,52.308 36.105,52.304 36.997,52.308 37.855,52.304 38.655,52.304 27.518,66.148 28.41,66.152 29.268,66.148 30.16,66.152 31.018,66.148 31.818,66.148 32.71,66.152 33.568,66.148 34.368,66.148 35.26,66.152 36.118,66.148 37.01,66.152 37.868,66.148 38.668,66.148 27.518,66.948 28.41,66.952 29.268,66.948 30.16,66.952 31.018,66.948 31.818,66.948 32.71,66.952 33.568,66.948 34.368,66.948 35.26,66.952 36.118,66.948 37.01,66.952 37.868,66.948 38.668,66.948 27.508,67.746 28.4,67.75 29.258,67.746 30.15,67.75 31.008,67.746 31.808,67.746 32.7,67.75 33.558,67.746 34.358,67.746 35.25,67.75 36.108,67.746 37,67.75 37.858,67.746 38.658,67.746 27.508,68.646 28.4,68.65 29.258,68.646 30.15,68.65 31.008,68.646 31.808,68.646 32.7,68.65 33.558,68.646 34.358,68.646 35.25,68.65 36.108,68.646 37,68.65 37.858,68.646 38.658,68.646 27.508,69.496 28.4,69.5 29.258,69.496 30.15,69.5 31.008,69.496 31.808,69.496 32.7,69.5 33.558,69.496 34.358,69.496 35.25,69.5 36.108,69.496 37,69.5 37.858,69.496 38.658,69.496
  other v2: 25.9,38.21 28.5,38.21 34.875,38.21 36.175,38.21 37.475,38.21 25.9,39.35 28.5,39.35 34.875,39.35 36.175,39.35 37.475,39.35 25.9,43.25 27.2,43.25 28.5,43.25 34.9,43.25 36.2,43.25 37.5,43.25 25.9,44.39 27.2,44.39 28.5,44.39 34.9,44.39 36.2,44.39 37.5,44.39
UC_En_Disable: CC49.1 RC7.1 RC12.2 UC1.4 | length 25.3
  Top Layer w0.2: RC7.1@2.95,14.65 2.95,13.7 3.695,12.955 v1(4.695,12.955) 4.695,12.9 CC49.1@7.3,12.9 RC12.2@9,12.9 ; v1(4.6,5.8) 5.35,5.8 7.1,4.05 7.1,3.6
  Top Layer w0.254: CC49.1@7.3,12.9 7.3,13.6 7.8,14.1 10.2,14.1 10.975,14.875 UC1.4@10.975,16.05
  Layer 2 w0.2: v1(4.6,5.8) 3.4,7 3.4,11.661 v1(4.695,12.955)
VBAT1: CC1.1 CC2.1 CC3.1 CC4.1 CC5.1 CC6.1 CC7.1 CC8.1 CC9.1 CC10.1 CC11.1 CC12.1 CC13.1 CC14.1 CC32.1 CC33.1 CC34.1 CC35.1 CC36.1 CC37.1 CC67.2 CC68.2 QC1.7 QC1.8 QC5.7 QC5.8 RC5.1 | length 4.8
  Bottom Layer w0.5: RC5.1@1.55,37.462 1.55,37.9 4.4,40.75 CC14.1@4.4,41.05
  other v1: 9.018,65.198 9.91,65.202 10.818,65.198 11.71,65.202 12.568,65.198 13.46,65.202 14.318,65.198 9.018,66.098 9.91,66.102 10.818,66.098 11.71,66.102 12.568,66.098 13.46,66.102 14.318,66.098 9.018,66.948 9.91,66.952 10.818,66.948 11.71,66.952 12.568,66.948 13.46,66.952 14.318,66.948 9.008,67.746 9.9,67.75 10.808,67.746 11.7,67.75 12.558,67.746 13.45,67.75 14.308,67.746 9.008,68.646 9.9,68.65 10.808,68.646 11.7,68.65 12.558,68.646 13.45,68.65 14.308,68.646 9.008,69.496 9.9,69.5 10.808,69.496 11.7,69.5 12.558,69.496 13.45,69.5 14.308,69.496
  other v2: 5.9,45.61 7.2,45.61 8.5,45.61 14.9,45.61 16.2,45.61 17.5,45.61 5.9,46.75 7.2,46.75 8.5,46.75 14.9,46.75 16.2,46.75 17.5,46.75
  other v4: 10.5,71.05 12,71.05 13.5,71.05 10.5,73.05 12,73.05 13.5,73.05
VBUS1: CC15.1 CC16.1 CC17.1 CC18.1 CC19.1 CC20.1 CC21.1 CC22.1 CC23.1 CC24.1 CC25.1 CC26.1 CC27.1 CC30.2 CC31.2 CC38.1 CC39.1 CC40.1 CC43.1 DC2.5 QC2.7 QC2.8 QC6.7 QC6.8 R5.2 UC1.20 | length 25.2
  Top Layer w0.2: R5.2@23.5,17.5 23.6,17.4 24.35,17.4 25,16.75 25,5.05 27.275,2.775 28.05,2 29,2 ; 26.65,22.3 CC31.2@27.95,23.6 ; QC2.7@26.875,46.85 QC2.7@27.425,46.3 ; QC6.7@34.8,46.85 v2(34.9,46.75)
  Top Layer w0.254: CC43.1@20.155,22.1 CC43.1@20.402,22.348
  Top Layer w0.5: 24.7,46.85 QC2.7@26.875,46.85 ; 33.7,46.85 QC6.7@34.8,46.85
  other v1: 27.303,4.964 28.103,4.964 29.753,4.964 30.553,4.964 28.896,4.968 27.294,5.762 28.094,5.762 28.886,5.766 29.744,5.762 30.544,5.762 27.294,6.662 28.094,6.662 28.886,6.666 29.744,6.662 30.544,6.662 27.294,7.512 28.094,7.512 28.886,7.516 29.744,7.512 30.544,7.512 27.294,8.362 28.094,8.362 28.886,8.366 29.744,8.362 30.544,8.362 27.303,20.164 28.103,20.164 28.896,20.168 29.753,20.164 30.553,20.164 27.294,20.962 28.094,20.962 28.886,20.966 29.744,20.962 30.544,20.962
  other v2: 25.9,45.61 27.2,45.61 28.5,45.61 34.9,45.61 36.2,45.61 37.5,45.61 25.9,46.75 27.2,46.75 28.5,46.75 36.2,46.75 37.5,46.75
  other v4: 27.5,1 29,1 30.5,1 27.5,3 29,3 30.5,3
VCC_DISCH: CC44.1 RC9.1 UC1.6 UC1.31 | length 19.2
  Top Layer w0.254: v1(10.99,14.1) 11.526,14.1 11.975,14.549 UC1.6@11.975,16.05 ; UC1.31@12.975,21.85 12.975,23.975 v1@13.25,24.25
  Layer 1 w0.2: v1(10.99,14.1) 12.75,15.86 12.75,23.9 v1(13.25,24.4)
  Bottom Layer w0.2: v1(10.99,14.1) 11.7,14.1 12.05,13.75 RC9.1@12.05,13.2 ; v1(13.25,24.4) 13.4,24.55 13.4,25.116 CC44.1@13.6,25.316
VFB: CC46.1 R5.1 R6.2 RC6.1 UC1.19 | length 21.1
  Top Layer w0.2: 21.45,3.5 21.45,6.95 24.548,10.048 24.548,10.764 24.548,12.336 24.548,14.852 R5.1@23.5,15.9 23.5,15.8 23.5,13.8 RC6.1@23.55,13.75
  Top Layer w0.254: UC1.19@18.475,16.05 CC46.1@20.055,16.05 ; CC46.1@20.205,15.9 23.3,15.9 R5.1@23.4,15.8
pads on no net: QC1.1 QC1.5 QC1.9 QC1.10 QC1.11 QC1.12 QC1.13 QC1.15 QC2.1 QC2.5 QC2.9 QC2.10 QC2.11 QC2.12 QC2.13 QC2.15 QC3.1 QC3.5 QC3.9 QC3.10 QC3.11 QC3.12 QC3.13 QC3.15 QC4.1 QC4.5 QC4.9 QC4.10 QC4.11 QC4.12 QC4.13 QC4.15 QC5.1 QC5.5 QC5.9 QC5.10 QC5.11 QC5.12 QC5.13 QC5.15 QC6.1 QC6.5 QC6.9 QC6.10 QC6.11 QC6.12 QC6.13 QC6.15 QC7.1 QC7.5 QC7.9 QC7.10 QC7.11 QC7.12 QC7.13 QC7.15 QC8.1 QC8.5 QC8.9 QC8.10 QC8.11 QC8.12 QC8.13 QC8.15 UC1.2 UC1.5 UC1.8 UC1.9 UC1.21 UC1.24 UC1.28 UC1.33 UC2.2 UC2.5
copper on no net:
  other v3: 4.335,6.85 4.835,6.85 5.335,6.85 4.335,7.85 4.835,7.85 5.335,7.85

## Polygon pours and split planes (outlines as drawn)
SGND on Layer 3 "48V_DISCH_OUT" (solid, remove dead copper, pour order 242): 23.818,37.45 40.318,37.45 40.318,3.259 39.218,2.159 23.818,2.159
SW2 on Layer 3 "LAYER_3_SW2_P285" (solid, pour order 285): 27.45,70 39.55,70 40,69.55 40,39.65 38.25,37.9 24,37.9 22.9,39 22.9,49.75 26.95,53.8 26.95,69.5
CSA_DISCH on Layer 3 "LAYER_3_CSA_DISCH_P212" (solid, pour order 212): 17.65,70 21.95,65.7 21.95,37.7 9.3,25.05 6.05,25.05 2.95,28.15 2.95,67 5.95,70
SGND on Layer 3 "LAYER_3_SGND_P266" (solid, remove dead copper, pour order 266): 4.3,23.05 1.7,23.05 0.5,24.25 0.5,71.5 4.3,71.5
CSB_DISCH on Layer 3 "LAYER_3_CSB_DISCH_P207" (solid, pour order 207): 18.5,69.65 18.85,70 26.05,70 26.55,69.5 26.55,54.75 24.95,53.15 19.65,53.15 18.5,54.3 18.5,69.6
SGND on Layer 3 "LAYER_3_SGND_P218" (solid, remove dead copper, pour order 218): 0.55,4.4 1.45,3.5 19.55,3.5 20.787,4.737 20.787,22.213 20.686,22.314 1.046,22.314 0.55,21.771
SW2 on Layer 4 "LAYER_4_SW2_P262" (solid, pour order 262): 27.45,70 39.55,70 40,69.55 40,48.7 39.15,47.85 21,47.85 20,48.85 20,50.45 22.05,52.5 26.45,52.5 26.95,53 26.95,69.5
CSB_DISCH on Layer 4 "LAYER_4_CSB_DISCH_P267" (solid, pour order 267): 18.5,69.65 18.85,70 26.05,70 26.55,69.5 26.55,51.6 25.9,50.95 19.45,50.95 18.5,51.9 18.5,69.6
SGND on Layer 4 "LAYER_4_SGND_P243" (solid, remove dead copper, pour order 243): 22.9,30.2 1.8,30.2 0.5,31.5 0.5,71.5 22.9,71.5
CSA_DISCH on Layer 4 "LAYER_4_CSA_DISCH_P256" (solid, pour order 256): 5.25,44.3 5.95,45 17.4,45 18.189,44.211 18.189,38.289 17.75,37.85 5.25,37.85
VBAT1 on Layer 4 "LAYER_4_VBAT1_P252" (solid, remove dead copper, pour order 252): 14.65,64.369 14.651,70.871 14.5,71.021 9.45,71.021 9.3,70.871 9.3,70.521 8.9,70.121 7.15,70.121 7.15,64.369
SGND on Layer 4 "LAYER_4_SGND_P213" (solid, remove dead copper, pour order 213): 2.3,3.85 2.65,3.5 19.5,3.5 20.787,4.787 20.787,22.213 20.686,22.314 2.45,22.314 2.3,22.15
VBUS1 on Layer 4 "48V_DISCH_OUT" (solid, remove dead copper, pour order 205): 38.35,49.4 40,47.75 40,8.279 38.849,7.127 35.377,7.127 34.5,6.25 34.5,1.9 23.4,1.9 23.4,47.6 25.2,49.4
SGND on Layer 6 "48V_DISCH_OUT" (solid, remove dead copper, pour order 286): 23.818,44.059 40.318,44.059 40.318,3.259 39.218,2.159 23.818,2.159
5V on Layer 6 "5V" (solid, remove dead copper, pour order 272): 3.9,10.25 3.9,9.1 4.15,8.85 5.45,8.85 5.7,9.1 5.7,10.2 5.4,10.5 4.15,10.5
SGND on Layer 6 "LAYER_6_SGND_P241" (solid, pour order 241): 0.9,71.5 5.25,71.5 6.75,70 39.5,70 40,69.5 40,36.05 39.55,35.6 1.95,35.6 0.5,37.05 0.5,71.1
VBAT1 on Layer 6 "LAYER_6_VBAT1_P214" (solid, pour order 214): 5.4,44.35 17.9,44.35 17.9,51.05 14.55,54.4 14.55,70.95 14.5,71 9.45,71 9.3,70.85 9.3,70.25 9.1,70.05 6.9,70.05 3.45,66.6 3.45,41.2 4.4,40.25 5,40.25 5.1,40.35 5.1,44.05
SGND on Layer 6 "LAYER_6_SGND_P217" (solid, remove dead copper, pour order 217): 2.3,3.85 2.65,3.5 19.55,3.5 20.787,4.737 20.787,22.213 20.686,22.314 2.45,22.314 2.3,22.15
CSA_DISCH on Layer 5 "LAYER_5_CSA_DISCH_P249" (solid, pour order 249): 15.35,69.5 15.85,70 17.85,70 18.2,69.65 18.2,53.3 17.6,52.7 16.1,52.7 15.35,53.45
VBAT1 on Layer 5 "LAYER_5_VBAT1_P270" (solid, remove dead copper, pour order 270): 14.645,64.35 14.645,70.852 14.495,71.002 9.445,71.002 9.295,70.852 9.295,70.502 8.895,70.102 7.145,70.102 7.145,64.35
CSB_DISCH on Layer 5 "LAYER_5_CSB_DISCH_P279" (solid, pour order 279): 18.5,69.65 18.85,70 26.05,70 26.55,69.5 26.55,53.5 26.05,53 19,53 18.5,53.5 18.5,69.6
SGND on Layer 5 "LAYER_5_SGND_P240" (solid, pour order 240): 0.9,71.5 5.25,71.5 6.75,70 39.5,70 40,69.5 40,24.2 38.9,23.1 0.9,23.1 0.5,23.5 0.5,71.1
SGND on Layer 5 "48V_DISCH_OUT" (solid, remove dead copper, pour order 204): 38.1,37.5 40,35.6 40,2.25 38.9,1.15 23.5,1.15 23.5,35.3 25.7,37.5
SGND on Layer 5 "SGND" (solid, remove dead copper, pour order 182): 15.15,8 16.095,8 16.3,7.795 16.3,6.152 15.498,5.35 6.35,5.35 4.1,7.6 4.1,10.85 3.5,11.45 3.35,11.6 3.35,13 3.5,13.15 8.7,13.15 10.753,11.097 12.047,11.097
SGND on Layer 5 "SGND" (solid, remove dead copper, pour order 199): 0.55,4.3 1.35,3.5 21.45,3.5 22.9,4.95 22.9,21.25 21.836,22.314 1.009,22.314 0.55,21.812
SGND on Bottom Layer "BOTTOM_LAYER_SGND_P264" (solid, pour order 264): 35.5,1.8 35.65,1.65 39.1,1.65 39.1,3.65 39.9,4.45 39.9,35.8 38.05,37.65 22.8,37.65 22.8,45.8 22.6,46 21.95,46 21.4,45.45 21.4,33.55 27.55,27.4 27.55,26.95 28.65,25.85 33.75,25.85 34.35,25.25 34.35,4.15 34.85,3.65 34.85,1.8 35.45,1.8 35.5,1.85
